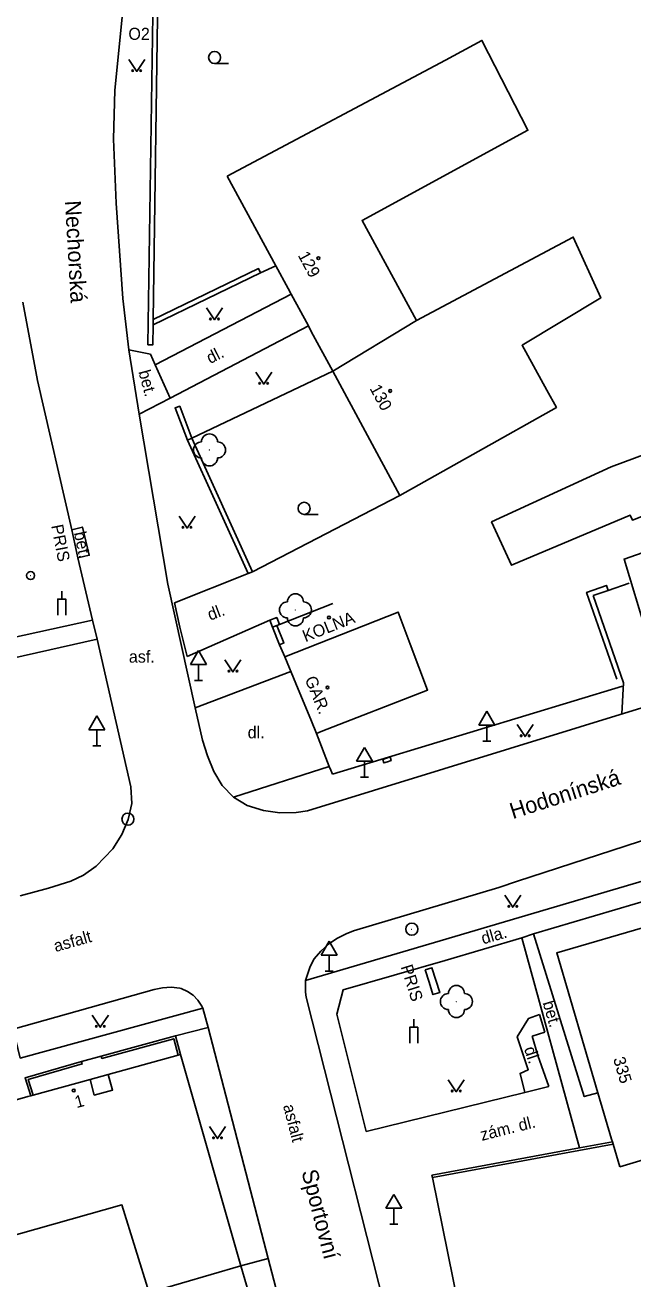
# Model space of a CAD drawing. Extents: x -577457 to -568404, y -1208466 to -1201387.
# Drawn here: x -574800.7 to -574762.8, y -1203993.7 to -1203915.5 of the extents above; entities that cross this region are included whole.
import ezdxf

# ---------------------------------------------------------------- set-up
doc = ezdxf.new("R2010")
doc.units = 0
for name, color, linetype in [('BUDOVY_MĚŘ', 7, 'Continuous'), ('BUDOVY_NEMĚŘ', 7, 'Continuous'), ('MAP_ZN_BP', 7, 'Continuous'), ('NÁZVY_ULIC_TOK_SMĚR', 7, 'Continuous'), ('OBVOD_PILÍŘE', 7, 'Continuous'), ('POMOC_POPIS', 7, 'Continuous'), ('ROZHRANÍ_PLOCH', 7, 'Continuous'), ('ZELEŇ', 7, 'Continuous'), ('ZN_BUDOV', 7, 'Continuous'), ('ZN_DOPLŇKOVÉ', 7, 'Continuous'), ('ZN_KULTUR', 7, 'Continuous'), ('Č_POPIS_ORIENT', 7, 'Continuous')]:
    doc.layers.add(name, color=color, linetype=linetype)

msp = doc.modelspace()

# ---------------------------------------------------------------- linework, layer by layer
at = {"layer": 'BUDOVY_MĚŘ'}
for points in [[(-574788.13, -1203924.94), (-574785.1, -1203930.53)], [(-574785.1, -1203930.53), (-574784.33, -1203931.96)], [(-574782.89, -1203934.63), (-574781.55, -1203937.11)], [(-574781.55, -1203937.11), (-574777.37, -1203944.85)], [(-574784.54, -1203954.92), (-574783.85, -1203956.59)], [(-574782.88, -1203958.93), (-574782.57, -1203959.69)], [(-574782.57, -1203959.69), (-574782.27, -1203959.57)], [(-574755.88, -1203969.96), (-574767.58, -1203973.37), (-574765.01, -1203982.1)], [(-574795.56, -1203980.96), (-574791.19, -1203979.76)], [(-574791.19, -1203979.76), (-574791.04, -1203979.72)], [(-574791.04, -1203979.72), (-574787.28, -1203992.89)], [(-574800.24, -1203982.25), (-574796.69, -1203981.27)], [(-574796.69, -1203981.27), (-574795.56, -1203980.96)], [(-574800.58, -1203982.34), (-574800.39, -1203982.29)], [(-574800.39, -1203982.29), (-574800.24, -1203982.25)], [(-574764.16, -1203985), (-574764.11, -1203985.16)], [(-574764.11, -1203985.16), (-574764.07, -1203985.3)], [(-574764.07, -1203985.3), (-574763.65, -1203986.72)]]:
    msp.add_lwpolyline(points, dxfattribs=at)
at = {"layer": 'BUDOVY_NEMĚŘ'}
for points in [[(-574788.13, -1203924.94), (-574774.52, -1203917.71), (-574772.25, -1203916.49), (-574769.38, -1203922.09), (-574779.72, -1203927.71), (-574776.32, -1203933.95), (-574781.55, -1203937.11)], [(-574776.32, -1203933.95), (-574766.55, -1203928.75), (-574764.84, -1203932.54), (-574769.74, -1203935.49), (-574768.2, -1203938.29), (-574767.6, -1203939.37), (-574777.37, -1203944.85)], [(-574743.36, -1203947.3), (-574746.27, -1203939.58), (-574748.31, -1203936.85), (-574753.44, -1203939.09), (-574764.19, -1203943.07), (-574771.64, -1203946.51), (-574770.41, -1203949.21), (-574763, -1203946.08), (-574762.86, -1203946.39), (-574751.67, -1203942.01), (-574750.84, -1203944.49), (-574761.84, -1203948.29), (-574763.38, -1203948.82), (-574761.99, -1203953.45)], [(-574784.54, -1203954.92), (-574777.48, -1203952.13), (-574776.72, -1203954.13), (-574775.64, -1203956.99), (-574782.27, -1203959.57)], [(-574753.96, -1203976.39), (-574753.45, -1203978.42), (-574757.52, -1203979.58), (-574756.17, -1203983.04), (-574758.16, -1203983.74), (-574757.74, -1203984.94), (-574763.65, -1203986.72)], [(-574787.28, -1203992.89), (-574792.84, -1203994.52), (-574793, -1203994.57), (-574794.7, -1203989.09), (-574802.13, -1203991.18), (-574804.73, -1203983.48)]]:
    msp.add_lwpolyline(points, dxfattribs=at)
at = {"layer": 'MAP_ZN_BP'}
for centre, radius in [((-574794.33, -1203965.041), 0.375), ((-574794.33, -1203965.041), 0.0005), ((-574776.62, -1203971.9), 0.375), ((-574776.62, -1203971.9), 0.0005)]:
    msp.add_circle(centre, radius, dxfattribs=at)
at = {"layer": 'OBVOD_PILÍŘE'}
for points in [[(-574778.43, -1203961.31), (-574778.36, -1203961.53), (-574778.14, -1203961.46), (-574777.91, -1203961.39), (-574777.98, -1203961.16), (-574778.43, -1203961.31)], [(-574775.79, -1203974.43), (-574775.54, -1203975.2), (-574775.3, -1203975.98), (-574774.88, -1203975.85), (-574775.37, -1203974.3), (-574775.79, -1203974.43)]]:
    msp.add_lwpolyline(points, dxfattribs=at)
at = {"layer": 'ROZHRANÍ_PLOCH'}
for points in [[(-574794.36, -1203911.69), (-574795.14, -1203919.59)], [(-574795.14, -1203919.59), (-574795.22, -1203922.64)], [(-574795.22, -1203922.64), (-574795.07, -1203926.64)], [(-574795.07, -1203926.64), (-574794.65, -1203932.58)], [(-574785.1, -1203930.53), (-574786.05, -1203930.98)], [(-574799.96, -1203937.69), (-574800.88, -1203932.8)], [(-574794.65, -1203932.58), (-574794.28, -1203935.77)], [(-574792.63, -1203936.71), (-574784.14, -1203932.31)], [(-574783.07, -1203934.29), (-574791.7, -1203938.79)], [(-574794.28, -1203935.77), (-574793.62, -1203939.79)], [(-574792.92, -1203936.05), (-574794.28, -1203935.77)], [(-574792.63, -1203936.71), (-574792.92, -1203936.05)], [(-574792.63, -1203936.71), (-574791.7, -1203938.79)], [(-574796.54, -1203952.64), (-574797.46, -1203948.74), (-574797.83, -1203947), (-574799.96, -1203937.69)], [(-574793.62, -1203939.79), (-574791.7, -1203938.79)], [(-574793.62, -1203939.79), (-574791.83, -1203950.38)], [(-574790.34, -1203941.29), (-574790.62, -1203941.42)], [(-574797.83, -1203947), (-574797.17, -1203946.83), (-574796.74, -1203948.59), (-574797.46, -1203948.74)], [(-574808.71, -1203949.55), (-574806.6, -1203954.84), (-574796.54, -1203952.64)], [(-574791.43, -1203951.55), (-574786.83, -1203949.73)], [(-574790.13, -1203958.09), (-574791.83, -1203950.38)], [(-574791.43, -1203951.55), (-574791.09, -1203953.06), (-574790.64, -1203954.9)], [(-574784.88, -1203952.9), (-574781.55, -1203951.6)], [(-574796.25, -1203953.82), (-574796.54, -1203952.64)], [(-574785.47, -1203952.63), (-574790.64, -1203954.9)], [(-574806.15, -1203956.05), (-574796.25, -1203953.82)], [(-574794.14, -1203963.02), (-574796.25, -1203953.82)], [(-574784.16, -1203955.84), (-574790.13, -1203958.09)], [(-574763.42, -1203956.53), (-574763.51, -1203958.48)], [(-574770.03, -1203968.91), (-574734.59, -1203957.4)], [(-574790.13, -1203958.09), (-574789.68, -1203960.12)], [(-574762.01, -1203958.02), (-574783.13, -1203964.51)], [(-574789.68, -1203960.12), (-574789.36, -1203961.1)], [(-574789.36, -1203961.1), (-574788.98, -1203962.06)], [(-574781.77, -1203961.76), (-574787.75, -1203963.67)], [(-574788.98, -1203962.06), (-574788.45, -1203962.94)], [(-574794.09, -1203964.06), (-574794.14, -1203963.02)], [(-574788.45, -1203962.94), (-574787.75, -1203963.67)], [(-574794.31, -1203965.07), (-574794.09, -1203964.06)], [(-574786.9, -1203964.18), (-574787.75, -1203963.67)], [(-574785.87, -1203964.49), (-574786.9, -1203964.18)], [(-574784.86, -1203964.64), (-574785.87, -1203964.49)], [(-574783.84, -1203964.63), (-574784.86, -1203964.64)], [(-574783.13, -1203964.51), (-574783.84, -1203964.63)], [(-574794.71, -1203966), (-574794.31, -1203965.07)], [(-574795.26, -1203966.88), (-574794.71, -1203966)], [(-574796.31, -1203967.97), (-574795.26, -1203966.88)], [(-574756.97, -1203967.35), (-574774.86, -1203972.63)], [(-574797.1, -1203968.54), (-574796.31, -1203967.97)], [(-574799.28, -1203969.34), (-574797.88, -1203968.9)], [(-574797.88, -1203968.9), (-574797.1, -1203968.54)], [(-574770.03, -1203968.91), (-574771.19, -1203969.3)], [(-574769.02, -1203972.19), (-574756.35, -1203968.45)], [(-574801.05, -1203969.83), (-574799.28, -1203969.34)], [(-574771.19, -1203969.3), (-574780.26, -1203972.01), (-574780.72, -1203972.19), (-574781.29, -1203972.48), (-574781.81, -1203972.84), (-574782.29, -1203973.26), (-574782.71, -1203973.74), (-574782.96, -1203974.23), (-574783.26, -1203975.09)], [(-574774.86, -1203972.63), (-574783.26, -1203975.09)], [(-574769.75, -1203972.44), (-574774.55, -1203973.86)], [(-574769.75, -1203972.44), (-574769.02, -1203972.19)], [(-574769.75, -1203972.44), (-574766.16, -1203985.54)], [(-574765.01, -1203982.1), (-574765.86, -1203982.34), (-574769.02, -1203972.19)], [(-574774.55, -1203973.86), (-574780.9, -1203975.68), (-574781.3, -1203977.2), (-574779.47, -1203984.51)], [(-574783.26, -1203975.09), (-574783.25, -1203975.82)], [(-574801.48, -1203978.14), (-574792.7, -1203975.65)], [(-574792.7, -1203975.65), (-574792.17, -1203975.55), (-574791.63, -1203975.52), (-574791.1, -1203975.58), (-574791.01, -1203975.6), (-574790.62, -1203975.78), (-574790.26, -1203976.02), (-574789.96, -1203976.33), (-574789.72, -1203976.69), (-574789.65, -1203976.83)], [(-574783.25, -1203975.82), (-574783.22, -1203976.14)], [(-574783.22, -1203976.14), (-574777.17, -1204000)], [(-574801.48, -1203978.14), (-574801.05, -1203979.94), (-574789.65, -1203976.83)], [(-574789.65, -1203976.83), (-574789.32, -1203978.02)], [(-574768.65, -1203977.22), (-574769.35, -1203977.47), (-574770.04, -1203978.62), (-574769.36, -1203980.66), (-574769.87, -1203980.89), (-574769.57, -1203982.09)], [(-574768.65, -1203977.22), (-574768.32, -1203978.33)], [(-574791.37, -1203978.54), (-574789.32, -1203978.02)], [(-574789.32, -1203978.02), (-574785.58, -1203992.43)], [(-574797.22, -1203980.15), (-574796, -1203979.81)], [(-574768.08, -1203981.7), (-574768.76, -1203979.78)], [(-574779.47, -1203984.51), (-574769.57, -1203982.09)], [(-574769.57, -1203982.09), (-574768.08, -1203981.7)], [(-574787.28, -1203992.89), (-574785.58, -1203992.43)], [(-574785.58, -1203992.43), (-574781.43, -1204008.33)]]:
    msp.add_lwpolyline(points, dxfattribs=at)
at = {"layer": 'ZELEŇ'}
for centre in [(-574789.24, -1203942.02), (-574783.88, -1203951.99), (-574773.84, -1203976.41)]:
    msp.add_circle(centre, 0.0005, dxfattribs=at)
for centre, start, end in [((-574789.74, -1203942.02), 89.99999, 269.99999), ((-574789.24, -1203941.52), 0, 179.99999), ((-574788.74, -1203942.02), 270, 89.99999), ((-574789.24, -1203942.52), 179.99999, 359.99999), ((-574784.38, -1203951.99), 89.99999, 269.99999), ((-574783.88, -1203951.49), 0, 179.99999), ((-574783.38, -1203951.99), 270, 89.99999), ((-574783.88, -1203952.49), 179.99999, 359.99999), ((-574774.34, -1203976.41), 89.99999, 269.99999), ((-574773.84, -1203975.91), 0, 179.99999), ((-574773.34, -1203976.41), 270, 89.99999), ((-574773.84, -1203976.91), 179.99999, 359.99999)]:
    msp.add_arc(centre, 0.5, start, end, dxfattribs=at)
at = {"layer": 'ZN_BUDOV'}
for centre in [(-574782.45, -1203930.06), (-574777.97, -1203938.34), (-574781.79, -1203952.47), (-574781.88, -1203956.83), (-574797.71, -1203981.96)]:
    msp.add_circle(centre, 0.0875, dxfattribs=at)
at = {"layer": 'ZN_DOPLŇKOVÉ'}
for p, q in [((-574798.46, -1203951.32), (-574798.46, -1203950.82)), ((-574789.92, -1203954.524), (-574790.42, -1203955.39)), ((-574789.92, -1203954.524), (-574789.42, -1203955.39)), ((-574790.42, -1203955.39), (-574789.42, -1203955.39)), ((-574789.92, -1203956.39), (-574789.92, -1203955.39)), ((-574790.17, -1203956.39), (-574789.67, -1203956.39)), ((-574796.26, -1203958.604), (-574796.76, -1203959.47)), ((-574796.26, -1203958.604), (-574795.76, -1203959.47)), ((-574771.94, -1203958.304), (-574772.44, -1203959.17)), ((-574771.94, -1203958.304), (-574771.44, -1203959.17)), ((-574796.76, -1203959.47), (-574795.76, -1203959.47)), ((-574796.26, -1203960.47), (-574796.26, -1203959.47)), ((-574772.44, -1203959.17), (-574771.44, -1203959.17)), ((-574771.94, -1203960.17), (-574771.94, -1203959.17)), ((-574772.19, -1203960.17), (-574771.69, -1203960.17)), ((-574796.51, -1203960.47), (-574796.01, -1203960.47)), ((-574779.58, -1203960.564), (-574780.08, -1203961.43)), ((-574779.58, -1203960.564), (-574779.08, -1203961.43)), ((-574780.08, -1203961.43), (-574779.08, -1203961.43)), ((-574779.58, -1203962.43), (-574779.58, -1203961.43)), ((-574779.83, -1203962.43), (-574779.33, -1203962.43)), ((-574781.78, -1203972.644), (-574782.28, -1203973.51)), ((-574781.78, -1203972.644), (-574781.28, -1203973.51)), ((-574782.28, -1203973.51), (-574781.28, -1203973.51)), ((-574781.78, -1203974.51), (-574781.78, -1203973.51)), ((-574782.03, -1203974.51), (-574781.53, -1203974.51)), ((-574776.5, -1203978.01), (-574776.5, -1203977.51)), ((-574777.75, -1203988.434), (-574778.25, -1203989.3)), ((-574777.75, -1203988.434), (-574777.25, -1203989.3)), ((-574778.25, -1203989.3), (-574777.25, -1203989.3)), ((-574777.75, -1203990.3), (-574777.75, -1203989.3)), ((-574778, -1203990.3), (-574777.5, -1203990.3))]:
    msp.add_line(p, q, dxfattribs=at)
for points in [[(-574792.74, -1203912.12), (-574793.08, -1203935.46), (-574792.78, -1203935.47), (-574792.76, -1203934.22)], [(-574792.74, -1203912.12), (-574792.44, -1203912.13), (-574792.76, -1203933.88)], [(-574792.76, -1203933.88), (-574786.18, -1203930.71), (-574786.05, -1203930.98)], [(-574792.76, -1203934.22), (-574786.05, -1203930.98)], [(-574784.33, -1203931.96), (-574784.14, -1203932.31)], [(-574784.14, -1203932.31), (-574783.07, -1203934.29)], [(-574792.76, -1203934.22), (-574792.76, -1203933.88)], [(-574783.07, -1203934.29), (-574782.89, -1203934.63)], [(-574781.55, -1203937.11), (-574790.34, -1203941.29)], [(-574790.34, -1203941.29), (-574791.1, -1203939.29), (-574791.39, -1203939.4), (-574790.62, -1203941.42)], [(-574790.62, -1203941.42), (-574786.83, -1203949.73)], [(-574790.34, -1203941.29), (-574786.55, -1203949.61), (-574786.83, -1203949.73)], [(-574786.55, -1203949.61), (-574777.37, -1203944.85)], [(-574763.84, -1203956.32), (-574765.72, -1203950.9), (-574764.48, -1203950.47), (-574764.37, -1203950.78)], [(-574765.3, -1203951.1), (-574764.37, -1203950.78)], [(-574764.37, -1203950.78), (-574763.06, -1203950.33)], [(-574798.71, -1203952.32), (-574798.71, -1203951.32), (-574798.21, -1203951.32), (-574798.21, -1203952.32)], [(-574763.42, -1203956.53), (-574765.3, -1203951.1)], [(-574784.88, -1203952.9), (-574785.05, -1203952.47), (-574785.47, -1203952.63)], [(-574785.31, -1203953.06), (-574785.47, -1203952.63)], [(-574785.31, -1203953.06), (-574785.03, -1203952.96)], [(-574784.88, -1203954.16), (-574785.31, -1203953.06)], [(-574785.03, -1203952.96), (-574784.88, -1203952.9)], [(-574784.88, -1203954.16), (-574784.6, -1203954.05), (-574785.03, -1203952.96)], [(-574784.88, -1203954.16), (-574784.54, -1203954.92)], [(-574783.85, -1203956.59), (-574782.88, -1203958.93)], [(-574781.57, -1203962.23), (-574763.48, -1203956.74)], [(-574781.77, -1203961.76), (-574782.57, -1203959.69)], [(-574781.68, -1203961.99), (-574781.77, -1203961.76)], [(-574781.57, -1203962.23), (-574781.68, -1203961.99)], [(-574776.75, -1203979.01), (-574776.75, -1203978.01), (-574776.25, -1203978.01), (-574776.25, -1203979.01)], [(-574769.11, -1203978.57), (-574768.32, -1203978.33)], [(-574796, -1203979.81), (-574791.37, -1203978.54)], [(-574791.19, -1203979.76), (-574791.47, -1203978.73), (-574795.95, -1203979.96), (-574796, -1203979.81)], [(-574791.37, -1203978.54), (-574791.04, -1203979.72)], [(-574769.11, -1203978.57), (-574768.76, -1203979.78)], [(-574800.39, -1203982.29), (-574800.74, -1203981.17), (-574797.22, -1203980.15)], [(-574797.22, -1203980.15), (-574797.18, -1203980.3), (-574800.55, -1203981.27), (-574800.24, -1203982.25)], [(-574795.56, -1203980.96), (-574795.29, -1203981.93), (-574796.43, -1203982.24), (-574796.69, -1203981.27)], [(-574765.01, -1203982.1), (-574764.16, -1203985)], [(-574803.14, -1203983.05), (-574800.58, -1203982.34)], [(-574764.07, -1203985.3), (-574775.34, -1203987.39)], [(-574766.16, -1203985.54), (-574764.11, -1203985.16)], [(-574775.34, -1203987.39), (-574775.37, -1203987.24), (-574766.16, -1203985.54)], [(-574775.34, -1203987.39), (-574772.78, -1204000)], [(-574787.28, -1203992.89), (-574786.58, -1203995.31)]]:
    msp.add_lwpolyline(points, dxfattribs=at)
for radius in [0.25, 0.0005]:
    msp.add_circle((-574800.4, -1203949.85), radius, dxfattribs=at)
at = {"layer": 'ZN_KULTUR'}
for p, q in [((-574788.92, -1203917.925), (-574788.045, -1203917.925)), ((-574783.34, -1203946.035), (-574782.465, -1203946.035))]:
    msp.add_line(p, q, dxfattribs=at)
for points in [[(-574794.28, -1203917.67), (-574793.78, -1203918.42), (-574793.28, -1203917.67)], [(-574789.43, -1203933.15), (-574788.93, -1203933.9), (-574788.43, -1203933.15)], [(-574786.36, -1203937.16), (-574785.86, -1203937.91), (-574785.36, -1203937.16)], [(-574791.14, -1203946.14), (-574790.64, -1203946.89), (-574790.14, -1203946.14)], [(-574788.28, -1203955.11), (-574787.78, -1203955.86), (-574787.28, -1203955.11)], [(-574770.05, -1203959.14), (-574769.55, -1203959.89), (-574769.05, -1203959.14)], [(-574770.82, -1203969.78), (-574770.32, -1203970.53), (-574769.82, -1203969.78)], [(-574796.55, -1203977.26), (-574796.05, -1203978.01), (-574795.55, -1203977.26)], [(-574774.35, -1203981.29), (-574773.85, -1203982.04), (-574773.35, -1203981.29)], [(-574789.24, -1203984.21), (-574788.74, -1203984.96), (-574788.24, -1203984.21)]]:
    msp.add_lwpolyline(points, dxfattribs=at)
for centre, radius in [((-574788.92, -1203917.55), 0.375), ((-574794.03, -1203918.37), 0.05), ((-574793.53, -1203918.37), 0.05), ((-574789.18, -1203933.85), 0.05), ((-574788.68, -1203933.85), 0.05), ((-574786.11, -1203937.86), 0.05), ((-574785.61, -1203937.86), 0.05), ((-574783.34, -1203945.66), 0.375), ((-574790.89, -1203946.84), 0.05), ((-574790.39, -1203946.84), 0.05), ((-574788.03, -1203955.81), 0.05), ((-574787.53, -1203955.81), 0.05), ((-574769.8, -1203959.84), 0.05), ((-574769.3, -1203959.84), 0.05), ((-574770.57, -1203970.48), 0.05), ((-574770.07, -1203970.48), 0.05), ((-574796.3, -1203977.96), 0.05), ((-574795.8, -1203977.96), 0.05), ((-574774.1, -1203981.99), 0.05), ((-574773.6, -1203981.99), 0.05), ((-574788.99, -1203984.91), 0.05), ((-574788.49, -1203984.91), 0.05)]:
    msp.add_circle(centre, radius, dxfattribs=at)

# ---------------------------------------------------------------- texts
at = {"layer": 'NÁZVY_ULIC_TOK_SMĚR'}
for s, rotation, p in [('Nechorská', 273.22999, (-574798.26, -1203926.49)), ('Hodonínská', 17.82999, (-574770.32, -1203965.04)), ('Sportovní', 284.54998, (-574783.51, -1203987.02))]:
    msp.add_text(s, height=1, rotation=rotation, dxfattribs=at).set_placement(p)
at = {"layer": 'POMOC_POPIS'}
for s, p in [('O2', (-574794.3, -1203916.45)), ('asf.', (-574794.27, -1203955.28)), ('dl.', (-574786.86, -1203960))]:
    msp.add_text(s, height=0.75, dxfattribs=at).set_placement(p)
for s, rotation, p in [('dl.', 26.83001, (-574789.2, -1203936.67)), ('bet.', 285.06999, (-574793.68, -1203937.14)), ('PRIS', 281.11, (-574799.12, -1203946.74)), ('bet.', 281.99997, (-574797.7, -1203947.19)), ('dl.', 20.75001, (-574789.2, -1203952.67)), ('KOLNA', 21.56, (-574783.26, -1203954.01)), ('GAR.', 292.40002, (-574783.31, -1203956.3)), ('asfalt', 15.83002, (-574798.84, -1203973.33)), ('dla.', 16.19001, (-574772.17, -1203972.85)), ('PRIS', 287.43998, (-574777.32, -1203974.24)), ('bet.', 286.34001, (-574768.47, -1203976.48)), ('dl.', 288.42999, (-574769.63, -1203979.35)), ('asfalt', 284.54998, (-574784.66, -1203982.91)), ('zám. dl.', 14.05998, (-574772.25, -1203985.1))]:
    msp.add_text(s, height=0.75, rotation=rotation, dxfattribs=at).set_placement(p)
at = {"layer": 'Č_POPIS_ORIENT'}
for s, rotation, p in [('129', 298.37998, (-574783.75, -1203929.88)), ('130', 298.37998, (-574779.27, -1203938.18)), ('335', 286.43999, (-574764.07, -1203979.98)), ('1', 15.36999, (-574797.53, -1203983.06))]:
    msp.add_text(s, height=0.75, rotation=rotation, dxfattribs=at).set_placement(p)

doc.saveas('drawing.dxf')
